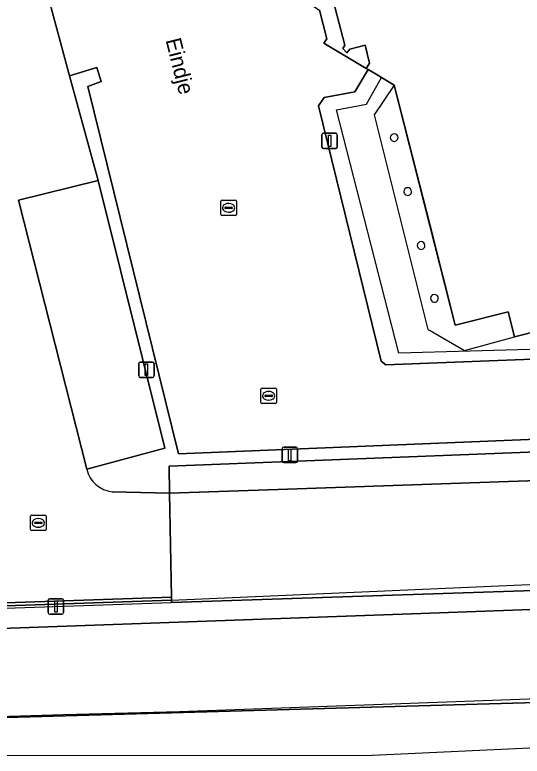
# Model space of a CAD drawing. Extents: x 160806 to 161707, y 383696 to 384148.
# Drawn here: x 160973.12 to 161005.97, y 383695.85 to 383743.85 of the extents above; entities that cross this region are included whole.
import ezdxf

# ---------------------------------------------------------------- set-up
doc = ezdxf.new("R2010")
doc.units = 0
for name, color, linetype in [('IMGEO_Dek', 7, 'Continuous'), ('IMGEO_Groenvoorziening', 7, 'Continuous'), ('IMGEO_Hek', 7, 'Continuous'), ('IMGEO_Lichtmast', 7, 'Continuous'), ('IMGEO_Muur', 7, 'Continuous'), ('IMGEO_Openbare_ruimte_label', 7, 'Continuous'), ('IMGEO_Pand', 7, 'Continuous'), ('IMGEO_Pand_overbouw', 7, 'Continuous'), ('IMGEO_Parkeervlak_gesloten', 7, 'Continuous'), ('IMGEO_Parkeervlak_open', 7, 'Continuous'), ('IMGEO_Rijbaan_lokaal_gesloten', 7, 'Continuous'), ('IMGEO_Rioolput', 7, 'Continuous'), ('IMGEO_Spoorbaan_halfverhard', 7, 'Continuous'), ('IMGEO_Struiken', 7, 'Continuous'), ('IMGEO_Voetpad_gesloten', 7, 'Continuous'), ('IMGEO_Voetpad_open', 7, 'Continuous')]:
    doc.layers.add(name, color=color, linetype=linetype)

msp = doc.modelspace()

# ---------------------------------------------------------------- linework, layer by layer
at = {"layer": 'IMGEO_Dek'}
for points in [[(161015.684, 383722.436), (160997.975, 383721.941), (160993.948, 383737.691), (160995.883, 383738.073), (160996.869, 383739.789), (160995.99, 383740.312), (160995.873, 383740.381), (160996.079, 383740.719), (160995.793, 383741.886), (160994.804, 383741.626), (160994.615, 383741.383), (160994.347, 383741.673), (160994.485, 383741.89), (160993.613, 383745.213)], [(160918.048, 383703.574), (160983.268, 383705.804), (160983.265, 383705.961), (161017.778, 383707.453)]]:
    msp.add_lwpolyline(points, dxfattribs=at)
at = {"layer": 'IMGEO_Groenvoorziening'}
for points in [[(161000, 383705.11), (161017.812, 383705.748), (161017.796, 383706.954), (160983.268, 383705.804), (160983.265, 383705.961), (160945.396, 383704.652), (160918.821, 383703.733), (160918.795, 383703.836), (160917.974, 383703.804), (160915.971, 383703.725), (160911.759, 383711.533), (160905.971, 383708.653), (160907.351, 383701.52), (160917.77, 383699.445), (160907.216, 383700.026), (160878.632, 383703.515), (160849.795, 383708.541), (160826.302, 383712.908), (160825.547, 383712.184)], [(160906.104, 383699.5), (160918.04, 383698.804), (160925.233, 383698.384), (160925.136, 383702.425), (161000, 383705.11)]]:
    msp.add_lwpolyline(points, dxfattribs=at)
at = {"layer": 'IMGEO_Hek'}
msp.add_lwpolyline([(161084.555, 383704.866), (161082.059, 383704.545), (161077.717, 383703.87), (161074.945, 383703.576), (161073.852, 383703.453), (161066.359, 383702.75), (161053.876, 383701.607), (161046.412, 383701.035), (161041.411, 383700.754), (161031.392, 383700.349), (161013.875, 383699.768), (161008.19, 383699.597), (160996.33, 383699.168), (160983.78, 383698.726), (160976.256, 383698.527), (160958.785, 383697.993), (160951.307, 383697.771), (160943.792, 383697.709), (160938.784, 383697.68), (160932.094, 383697.764)], dxfattribs=at)
at = {"layer": 'IMGEO_Lichtmast'}
for p, q in [((160993.004, 383735.289), (160993.004, 383736.089)), ((160993.004, 383736.089), (160993.004, 383735.289)), ((160993.104, 383736.189), (160993.894, 383736.189)), ((160993.894, 383736.189), (160993.104, 383736.189)), ((160993.994, 383736.089), (160993.994, 383735.289)), ((160993.994, 383735.289), (160993.994, 383736.089)), ((160993.894, 383735.189), (160993.104, 383735.189)), ((160993.104, 383735.189), (160993.894, 383735.189)), ((160981.146, 383720.467), (160981.146, 383721.267)), ((160981.146, 383721.267), (160981.146, 383720.467)), ((160981.246, 383721.367), (160982.036, 383721.367)), ((160982.036, 383721.367), (160981.246, 383721.367)), ((160982.136, 383721.267), (160982.136, 383720.467)), ((160982.136, 383720.467), (160982.136, 383721.267)), ((160982.036, 383720.367), (160981.246, 383720.367)), ((160981.246, 383720.367), (160982.036, 383720.367)), ((160990.528, 383715.857), (160991.318, 383715.857)), ((160991.318, 383715.857), (160990.528, 383715.857)), ((160990.428, 383714.957), (160990.428, 383715.757)), ((160990.428, 383715.757), (160990.428, 383714.957)), ((160991.418, 383715.757), (160991.418, 383714.957)), ((160991.418, 383714.957), (160991.418, 383715.757)), ((160991.318, 383714.857), (160990.528, 383714.857)), ((160990.528, 383714.857), (160991.318, 383714.857)), ((160975.282, 383705.143), (160975.282, 383705.943)), ((160975.282, 383705.943), (160975.282, 383705.143)), ((160975.382, 383706.043), (160976.172, 383706.043)), ((160976.172, 383706.043), (160975.382, 383706.043)), ((160976.272, 383705.943), (160976.272, 383705.143)), ((160976.272, 383705.143), (160976.272, 383705.943)), ((160976.172, 383705.043), (160975.382, 383705.043)), ((160975.382, 383705.043), (160976.172, 383705.043))]:
    msp.add_line(p, q, dxfattribs=at)
for points in [[(160993.424, 383736.064), (160993.574, 383736.064), (160993.574, 383735.314), (160993.424, 383735.314), (160993.424, 383736.064)], [(160981.566, 383721.242), (160981.716, 383721.242), (160981.716, 383720.492), (160981.566, 383720.492), (160981.566, 383721.242)], [(160990.848, 383715.732), (160990.998, 383715.732), (160990.998, 383714.982), (160990.848, 383714.982), (160990.848, 383715.732)], [(160975.702, 383705.918), (160975.852, 383705.918), (160975.852, 383705.168), (160975.702, 383705.168), (160975.702, 383705.918)]]:
    msp.add_lwpolyline(points, dxfattribs=at)
for centre, start, end in [((160993.104, 383736.089), 90, 180), ((160993.104, 383736.089), 90, 180), ((160993.894, 383736.089), 0, 90), ((160993.894, 383736.089), 360, 90), ((160993.104, 383735.289), 180, 270), ((160993.104, 383735.289), 180, 270), ((160993.894, 383735.289), 270, 0), ((160993.894, 383735.289), 270, 0), ((160981.246, 383721.267), 90, 180), ((160981.246, 383721.267), 90, 180), ((160982.036, 383721.267), 0, 90), ((160982.036, 383721.267), 360, 90), ((160981.246, 383720.467), 180, 270), ((160981.246, 383720.467), 180, 270), ((160982.036, 383720.467), 270, 0), ((160982.036, 383720.467), 270, 0), ((160990.528, 383715.757), 90, 180), ((160990.528, 383715.757), 90, 180), ((160991.318, 383715.757), 0, 90), ((160991.318, 383715.757), 360, 90), ((160990.528, 383714.957), 180, 270), ((160990.528, 383714.957), 180, 270), ((160991.318, 383714.957), 270, 0), ((160991.318, 383714.957), 270, 0), ((160975.382, 383705.943), 90, 180), ((160975.382, 383705.943), 90, 180), ((160976.172, 383705.943), 0, 90), ((160976.172, 383705.943), 360, 90), ((160975.382, 383705.143), 180, 270), ((160975.382, 383705.143), 180, 270), ((160976.172, 383705.143), 270, 0), ((160976.172, 383705.143), 270, 0)]:
    msp.add_arc(centre, 0.1, start, end, dxfattribs=at)
at = {"layer": 'IMGEO_Muur'}
msp.add_lwpolyline([(161017.812, 383705.748), (161000, 383705.11), (160925.136, 383702.425), (160925.233, 383698.384), (160918.04, 383698.804)], dxfattribs=at)
at = {"layer": 'IMGEO_Pand'}
msp.add_lwpolyline([(160993.613, 383745.213), (160994.485, 383741.89), (160994.347, 383741.673), (160994.615, 383741.383), (160994.804, 383741.626), (160995.793, 383741.886), (160996.079, 383740.719), (160995.873, 383740.381), (160995.99, 383740.312), (160996.519, 383739.997), (160996.869, 383739.789), (160997.685, 383739.303), (161000, 383730.195), (161001.638, 383723.751), (161005.059, 383724.621), (161005.472, 383722.996), (161009.147, 383723.93)], dxfattribs=at)
for centre, start, end in [((160997.679, 383735.901), 0.2296, 179.7704), ((160997.679, 383735.901), 179.7713, 0.2287), ((160998.556, 383732.407), 0.2296, 179.7704), ((160998.556, 383732.407), 179.7713, 0.2287), ((160999.421, 383728.913), 0.2296, 179.7704), ((160999.421, 383728.913), 179.7713, 0.2287), ((161000.287, 383725.491), 0.2296, 179.7704), ((161000.287, 383725.491), 179.7713, 0.2287)]:
    msp.add_arc(centre, 0.25, start, end, dxfattribs=at)
at = {"layer": 'IMGEO_Pand_overbouw'}
for points in [[(160994.095, 383747.26), (160992.471, 383744.38), (160992.846, 383744.157), (160993.322, 383742.286), (160993.135, 383742.01), (160995.873, 383740.381), (160996.079, 383740.719), (160995.793, 383741.886), (160994.804, 383741.626), (160994.615, 383741.383), (160994.347, 383741.673), (160994.485, 383741.89), (160993.613, 383745.213), (160993.358, 383745.414), (160993.622, 383745.772), (160993.877, 383745.634), (160994.802, 383745.868), (160994.541, 383746.997)], [(160997.685, 383739.303), (160996.393, 383737.381), (160999.86, 383723.481), (161000, 383723.401), (161002.232, 383722.122), (161005.472, 383722.996), (161005.059, 383724.621), (161001.638, 383723.751)]]:
    msp.add_lwpolyline(points, close=True, dxfattribs=at)
at = {"layer": 'IMGEO_Parkeervlak_gesloten'}
for points in [[(160975.479, 383744.309), (160976.667, 383739.892), (160978.422, 383740.436), (160978.72, 383739.522), (160977.847, 383739.202), (160983.71, 383715.431), (161017.446, 383716.817)], [(161020.567, 383722.095), (160997.147, 383721.192), (160996.841, 383721.416), (160992.783, 383737.964), (160993.141, 383738.5), (160995.138, 383738.871), (160995.99, 383740.312), (160995.873, 383740.381), (160993.135, 383742.01), (160993.322, 383742.286), (160992.846, 383744.157)]]:
    msp.add_lwpolyline(points, dxfattribs=at)
msp.add_lwpolyline([(160978.516, 383733.118), (160973.367, 383731.844), (160977.776, 383714.424), (160982.823, 383715.796)], close=True, dxfattribs=at)
at = {"layer": 'IMGEO_Parkeervlak_open'}
for points in [[(160997.685, 383739.303), (160996.869, 383739.789), (160996.519, 383739.997), (160995.99, 383740.312), (160995.873, 383740.381), (160996.079, 383740.719), (160995.793, 383741.886), (160994.804, 383741.626), (160994.615, 383741.383), (160994.347, 383741.673), (160994.485, 383741.89), (160993.613, 383745.213)], [(161009.147, 383723.93), (161005.472, 383722.996), (161005.059, 383724.621), (161001.638, 383723.751), (161000, 383730.195), (160997.685, 383739.303)], [(160945.396, 383704.652), (160983.265, 383705.961), (160983.268, 383705.804), (161017.796, 383706.954), (161017.786, 383707.23), (161017.778, 383707.453), (161017.526, 383714.059), (161017.462, 383716.268), (161040.763, 383717.379), (161042.298, 383717.413), (161043.818, 383719.857), (161045.121, 383722.55), (161044.318, 383723.055)]]:
    msp.add_lwpolyline(points, dxfattribs=at)
for centre, start, end in [((160997.679, 383735.901), 0.2296, 179.7704), ((160997.679, 383735.901), 179.7713, 0.2287), ((160998.556, 383732.407), 0.2296, 179.7704), ((160998.556, 383732.407), 179.7713, 0.2287), ((160999.421, 383728.913), 0.2296, 179.7704), ((160999.421, 383728.913), 179.7713, 0.2287), ((161000.287, 383725.491), 0.2296, 179.7704), ((161000.287, 383725.491), 179.7713, 0.2287)]:
    msp.add_arc(centre, 0.25, start, end, dxfattribs=at)
at = {"layer": 'IMGEO_Rijbaan_lokaal_gesloten'}
for points in [[(160978.516, 383733.118), (160976.667, 383739.892), (160975.479, 383744.309), (160974.285, 383748.798), (160971.205, 383761.352), (160960.762, 383758.727), (160964.044, 383745.648)], [(160977.776, 383714.424), (160973.367, 383731.844), (160978.516, 383733.118)], [(160945.3, 383707.13), (160945.346, 383704.857), (160983.262, 383706.136), (160983.144, 383712.87), (160979.43, 383712.971)]]:
    msp.add_lwpolyline(points, dxfattribs=at)
msp.add_lwpolyline([(161017.526, 383714.059), (160990.144, 383713.112), (160983.144, 383712.87), (160983.262, 383706.136), (160983.265, 383705.961), (161017.778, 383707.453)], close=True, dxfattribs=at)
msp.add_arc((160979.625, 383714.861), 1.9, 193.3042, 264.0987, dxfattribs=at)
at = {"layer": 'IMGEO_Rioolput'}
for p, q in [((160986.463, 383730.926), (160986.463, 383731.778)), ((160986.538, 383731.852), (160987.39, 383731.852)), ((160987.464, 383731.778), (160987.464, 383730.926)), ((160986.722, 383731.346), (160986.722, 383731.358)), ((160987.16, 383731.309), (160986.762, 383731.309)), ((160986.765, 383731.395), (160987.163, 383731.395)), ((160986.951, 383731.632), (160986.976, 383731.632)), ((160987.206, 383731.358), (160987.206, 383731.346)), ((160987.39, 383730.852), (160986.538, 383730.852)), ((160986.974, 383731.072), (160986.949, 383731.072)), ((160989.053, 383718.755), (160989.053, 383719.607)), ((160989.128, 383719.681), (160989.98, 383719.681)), ((160989.355, 383719.224), (160989.753, 383719.224)), ((160989.541, 383719.461), (160989.566, 383719.461)), ((160990.054, 383719.607), (160990.054, 383718.755)), ((160989.312, 383719.175), (160989.312, 383719.187)), ((160989.75, 383719.138), (160989.352, 383719.138)), ((160989.564, 383718.901), (160989.539, 383718.901)), ((160989.796, 383719.187), (160989.796, 383719.175)), ((160989.98, 383718.681), (160989.128, 383718.681)), ((160974.142, 383710.527), (160974.142, 383711.379)), ((160974.217, 383711.453), (160975.069, 383711.453)), ((160974.63, 383711.233), (160974.655, 383711.233)), ((160975.143, 383711.379), (160975.143, 383710.527)), ((160974.401, 383710.947), (160974.401, 383710.959)), ((160974.839, 383710.91), (160974.441, 383710.91)), ((160974.444, 383710.996), (160974.842, 383710.996)), ((160974.653, 383710.673), (160974.628, 383710.673)), ((160974.885, 383710.959), (160974.885, 383710.947)), ((160975.069, 383710.453), (160974.217, 383710.453))]:
    msp.add_line(p, q, dxfattribs=at)
for points in [[(160986.463, 383730.926), (160986.463, 383731.778)], [(160986.538, 383731.852), (160987.39, 383731.852)], [(160987.464, 383731.778), (160987.464, 383730.926)], [(160987.39, 383730.852), (160986.538, 383730.852)], [(160989.053, 383718.755), (160989.053, 383719.607)], [(160989.128, 383719.681), (160989.98, 383719.681)], [(160990.054, 383719.607), (160990.054, 383718.755)], [(160989.98, 383718.681), (160989.128, 383718.681)], [(160974.142, 383710.527), (160974.142, 383711.379)], [(160974.217, 383711.453), (160975.069, 383711.453)], [(160975.143, 383711.379), (160975.143, 383710.527)], [(160975.069, 383710.453), (160974.217, 383710.453)]]:
    msp.add_lwpolyline(points, dxfattribs=at)
for centre, radius, start, end in [((160986.54, 383731.776), 0.0765, 91.552, 178.448), ((160986.54, 383731.776), 0.0765, 91.552, 178.448), ((160987.388, 383731.776), 0.0765, 1.552, 88.448), ((160987.388, 383731.776), 0.0765, 1.552, 88.448), ((160986.762, 383731.355), 0.0403, 85.8775, 175.7526), ((160986.759, 383731.345), 0.0366, 178.938, 274.7102), ((160987.163, 383731.352), 0.043, 264.8664, 352.4533), ((160987.167, 383731.357), 0.0386, 1.7309, 96.639), ((160986.54, 383730.928), 0.0765, 181.552, 268.448), ((160986.54, 383730.928), 0.0765, 181.552, 268.448), ((160987.388, 383730.928), 0.0765, 271.552, 358.448), ((160987.388, 383730.928), 0.0765, 271.552, 358.448), ((160989.13, 383719.605), 0.0765, 91.552, 178.448), ((160989.13, 383719.605), 0.0765, 91.552, 178.448), ((160989.352, 383719.184), 0.0403, 85.8775, 175.7526), ((160989.757, 383719.186), 0.0386, 1.7309, 96.639), ((160989.978, 383719.605), 0.0765, 1.552, 88.448), ((160989.978, 383719.605), 0.0765, 1.552, 88.448), ((160989.13, 383718.757), 0.0765, 181.552, 268.448), ((160989.13, 383718.757), 0.0765, 181.552, 268.448), ((160989.349, 383719.174), 0.0366, 178.938, 274.7102), ((160989.753, 383719.181), 0.043, 264.8664, 352.4533), ((160989.978, 383718.757), 0.0765, 271.552, 358.448), ((160989.978, 383718.757), 0.0765, 271.552, 358.448), ((160974.219, 383711.377), 0.0765, 91.552, 178.448), ((160974.219, 383711.377), 0.0765, 91.552, 178.448), ((160975.067, 383711.377), 0.0765, 1.552, 88.448), ((160975.067, 383711.377), 0.0765, 1.552, 88.448), ((160974.441, 383710.956), 0.0403, 85.8775, 175.7526), ((160974.438, 383710.946), 0.0366, 178.938, 274.7102), ((160974.842, 383710.953), 0.043, 264.8664, 352.4533), ((160974.846, 383710.958), 0.0386, 1.7309, 96.639), ((160974.219, 383710.529), 0.0765, 181.552, 268.448), ((160974.219, 383710.529), 0.0765, 181.552, 268.448), ((160975.067, 383710.529), 0.0765, 271.552, 358.448), ((160975.067, 383710.529), 0.0765, 271.552, 358.448)]:
    msp.add_arc(centre, radius, start, end, dxfattribs=at)
for centre, major_axis, ratio, start_param, end_param in [((160986.95, 383731.352), (-0.387, 0.002), 0.722429, 4.712389, 7.853982), ((160986.975, 383731.352), (-0.39, 0.002), 0.717154, 1.570796, 4.712389), ((160989.54, 383719.181), (-0.387, 0.002), 0.722429, 4.712389, 7.853982), ((160989.565, 383719.181), (-0.39, 0.002), 0.717154, 1.570796, 4.712389), ((160974.629, 383710.953), (-0.387, 0.002), 0.722429, 4.712389, 7.853982), ((160974.654, 383710.953), (-0.39, 0.002), 0.717154, 1.570796, 4.712389)]:
    msp.add_ellipse(centre, major_axis=major_axis, ratio=ratio, start_param=start_param, end_param=end_param, dxfattribs=at)
at = {"layer": 'IMGEO_Spoorbaan_halfverhard'}
msp.add_lwpolyline([(160821.504, 383711.182), (160875.894, 383702.41), (160922.821, 383695.85), (160996.257, 383695.919), (161042.213, 383698.051), (161092.512, 383703.206), (161091.717, 383705.343), (161091.615, 383705.332), (161082.438, 383704.359), (161077.717, 383703.87), (161074.945, 383703.576), (161073.852, 383703.453), (161066.359, 383702.75), (161050.171, 383701.028), (161040.034, 383700.432), (161009.181, 383699.4), (160949.68, 383697.713), (160939.829, 383697.51), (160932.571, 383697.47), (160925.335, 383698.113), (160925.233, 383698.384), (160918.04, 383698.804), (160906.104, 383699.5)], dxfattribs=at)
at = {"layer": 'IMGEO_Struiken'}
msp.add_lwpolyline([(161073.019, 383710.895), (161072.742, 383713.37), (161046.242, 383708.336), (161045.034, 383708.106), (161044.427, 383708.097), (161044.433, 383707.93), (161017.796, 383706.954), (161017.812, 383705.748), (161000, 383705.11), (160925.136, 383702.425), (160925.233, 383698.384), (160925.335, 383698.113), (160932.571, 383697.47), (160939.829, 383697.51), (160949.68, 383697.713), (161009.181, 383699.4), (161040.034, 383700.432), (161050.171, 383701.028), (161066.359, 383702.75), (161073.852, 383703.453), (161073.702, 383704.795), (161073.241, 383708.907), (161057.615, 383707.411), (161067.155, 383709.715)], close=True, dxfattribs=at)
at = {"layer": 'IMGEO_Voetpad_gesloten'}
for points in [[(161047.689, 383726.041), (161047.527, 383726.542), (161047.162, 383727.994), (161034.181, 383780.096), (161003.066, 383772.21), (161015.684, 383722.436), (160997.975, 383721.941), (160993.948, 383737.691), (160995.883, 383738.073), (160996.869, 383739.789), (160995.99, 383740.312), (160995.138, 383738.871), (160993.141, 383738.5), (160992.783, 383737.964), (160996.841, 383721.416), (160997.147, 383721.192), (161020.567, 383722.095)], [(161017.47, 383715.97), (161017.462, 383716.268), (161017.446, 383716.817), (160983.71, 383715.431), (160977.847, 383739.202), (160978.72, 383739.522), (160978.422, 383740.436), (160976.667, 383739.892), (160978.516, 383733.118), (160982.823, 383715.796), (160977.776, 383714.424)], [(160979.43, 383712.971), (160983.144, 383712.87), (160983.113, 383714.631), (161017.47, 383715.97)], [(160918.048, 383703.574), (160983.268, 383705.804), (160983.265, 383705.961), (160983.262, 383706.136), (160945.346, 383704.857)]]:
    msp.add_lwpolyline(points, dxfattribs=at)
msp.add_arc((160979.625, 383714.861), 1.9, 193.3042, 264.0987, dxfattribs=at)
at = {"layer": 'IMGEO_Voetpad_open'}
msp.add_lwpolyline([(161017.47, 383715.97), (160983.113, 383714.631), (160983.144, 383712.87), (160990.144, 383713.112), (161017.526, 383714.059)], close=True, dxfattribs=at)

# ---------------------------------------------------------------- texts
at = {"layer": 'IMGEO_Openbare_ruimte_label'}
msp.add_text('Eindje', height=1, rotation=284.064, dxfattribs=at).set_placement((160982.877, 383742.213))

doc.saveas('drawing.dxf')
